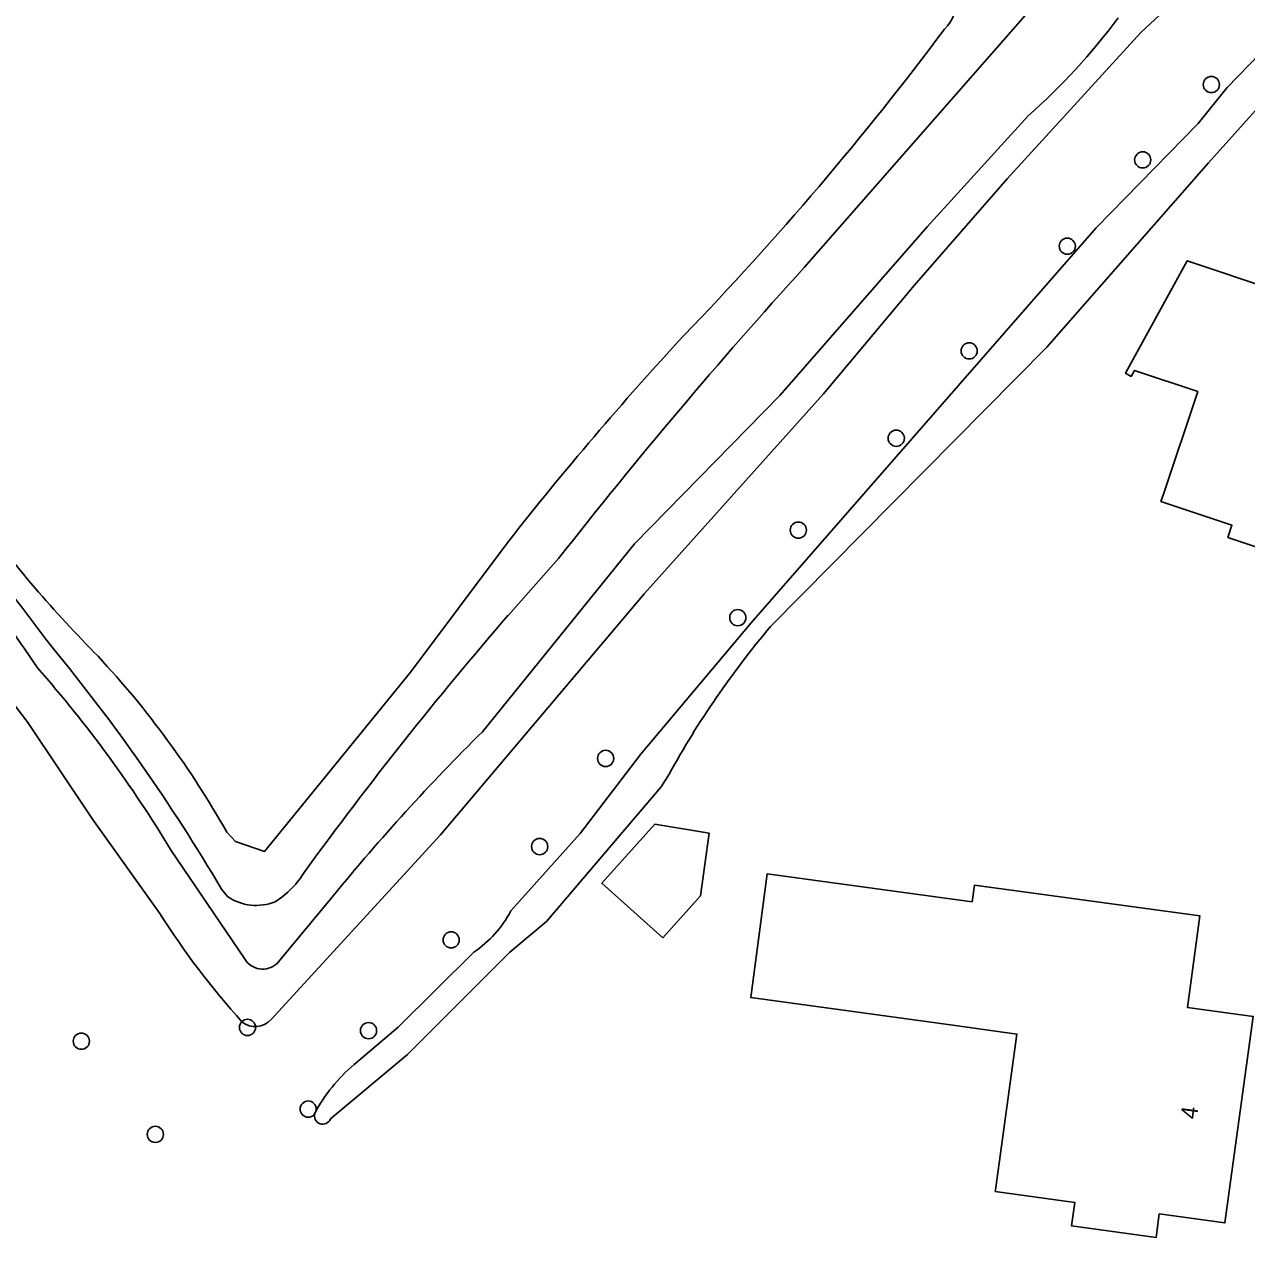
# Model space of a CAD drawing. Extents: x 161696 to 162377, y 380761 to 381673.
# Drawn here: x 161820.6 to 161894.4, y 380889 to 380962.2 of the extents above; entities that cross this region are included whole.
import ezdxf

# ---------------------------------------------------------------- set-up
doc = ezdxf.new("R2010")
doc.units = 0
for name, color, linetype in [('IMGEO_Boom', 7, 'Continuous'), ('IMGEO_Groenvoorziening', 7, 'Continuous'), ('IMGEO_Meer_plas_ven_vijver', 7, 'Continuous'), ('IMGEO_Pand', 7, 'Continuous'), ('IMGEO_Pand_nummerreeks', 7, 'Continuous')]:
    doc.layers.add(name, color=color, linetype=linetype)

msp = doc.modelspace()

# ---------------------------------------------------------------- linework, layer by layer
at = {"layer": 'IMGEO_Boom'}
for centre in [(161892.316, 380958.613), (161888.173, 380954.061), (161883.615, 380948.847), (161877.691, 380942.522), (161873.285, 380937.245), (161867.37, 380931.695), (161863.713, 380926.409), (161855.73, 380917.904), (161851.744, 380912.578), (161846.4, 380906.942), (161834.099, 380901.653), (161841.411, 380901.459), (161824.062, 380900.819), (161837.765, 380896.719), (161828.531, 380895.19)]:
    msp.add_circle(centre, 0.489, dxfattribs=at)
at = {"layer": 'IMGEO_Groenvoorziening'}
for points in [[(161890.992, 380963.938), (161889.178, 380962.795), (161888.049, 380961.767), (161879.992, 380952.907), (161874.365, 380946.481), (161868.891, 380939.924), (161858.069, 380927.868), (161845.75, 380913.287), (161835.524, 380902.132)], [(161828.8, 380908.528), (161824.729, 380914.242), (161820.832, 380920.076), (161816.792, 380925.368), (161812.56, 380930.508)], [(161832.847, 380913.452), (161833.367, 380912.893), (161835.131, 380912.284), (161843.974, 380923.135), (161849.842, 380930.991)]]:
    msp.add_lwpolyline(points, dxfattribs=at)
for centre, radius, start, end in [((161874.423, 380963.719), 2.502, 315.23013, 55.38582), ((161721.268, 381077.819), 193.462, 316.01453, 323.20983), ((162011.017, 380804.458), 204.91, 137.28297, 141.86566), ((161880.505, 380979.022), 78.053, 216.46984, 224.74709), ((161784.161, 380885.964), 55.91, 29.44897, 42.9712), ((161871.423, 380935.736), 50.566, 212.5521, 221.87896), ((161834.566, 380903.002), 1.294, 232.17583, 317.7467)]:
    msp.add_arc(centre, radius, start, end, dxfattribs=at)
at = {"layer": 'IMGEO_Meer_plas_ven_vijver'}
for points in [[(161881.363, 380963.1), (161867.724, 380947.551)], [(161898.49, 380960.955), (161892.147, 380953.884), (161882.378, 380942.741), (161865.694, 380925.863)], [(161891.512, 380956.258), (161893.282, 380958.444), (161895.242, 380960.46)], [(161848.287, 380919.518), (161857.473, 380930.863), (161866.252, 380939.835), (161875.146, 380950.013), (161881.261, 380956.728)], [(161849.996, 380908.69), (161854.199, 380913.376), (161857.841, 380918.147), (161864.514, 380926.091), (161885.359, 380949.949), (161891.512, 380956.258)], [(161852.893, 380929.987), (161849.854, 380926.552)], [(161859.566, 380916.954), (161859.086, 380916.182), (161852.157, 380908.058), (161849.953, 380906.192), (161843.758, 380900.025), (161839.114, 380896.129)], [(161829.498, 380912.335), (161833.913, 380905.812)], [(161832.887, 380909.553), (161832.531, 380910.004)], [(161835.867, 380905.495), (161839.292, 380909.632)], [(161840.535, 380899.404), (161843.2, 380901.675), (161847.767, 380906.206)]]:
    msp.add_lwpolyline(points, dxfattribs=at)
for centre, radius, start, end in [((161855.472, 380985.852), 38.901, 311.52417, 323.37165), ((162097.685, 380738.329), 310.895, 137.70358, 141.94108), ((161562.489, 380729.187), 325.109, 36.95355, 40.36514), ((161742.127, 380869.892), 95.642, 34.00137, 42.69487), ((162023.218, 380776.27), 229.434, 139.07933, 144.01499), ((161907.228, 380890.732), 54.4, 139.77431, 151.1819), ((161733.625, 380851.665), 114.83, 30.53384, 39.4523), ((161763.115, 380872.221), 77.561, 31.14362, 41.26455), ((161940.338, 380826.728), 130.703, 134.77098, 140.63262), ((161832.655, 380914.08), 5.756, 302.77592, 328.57957), ((161834.628, 380912.153), 3.129, 236.18645, 291.42543), ((161844.156, 380911.688), 6.565, 303.37135, 332.82266), ((161835.019, 380906.449), 1.276, 209.9344, 311.63583), ((161846.792, 380891.936), 9.743, 129.96068, 152.3411), ((161838.643, 380896.306), 0.503, 162.28511, 339.44102)]:
    msp.add_arc(centre, radius, start, end, dxfattribs=at)
at = {"layer": 'IMGEO_Pand'}
for points in [[(161904.606, 380949.376), (161901.633, 380940.472), (161900.683, 380940.788), (161900.051, 380938.888), (161905.097, 380937.205), (161902.371, 380929.046), (161898.075, 380930.482), (161897.828, 380929.743), (161893.314, 380931.252), (161893.562, 380931.992), (161889.275, 380933.425), (161889.424, 380933.871), (161891.494, 380940.065), (161887.672, 380941.343), (161887.466, 380940.984), (161887.136, 380941.173), (161890.851, 380947.961), (161896.162, 380946.187), (161897.967, 380951.593), (161904.606, 380949.376)], [(161861.989, 380913.379), (161861.455, 380909.606), (161859.179, 380907.066), (161855.499, 380910.364), (161858.694, 380913.929), (161861.989, 380913.379)], [(161877.874, 380909.249), (161878.009, 380910.24), (161891.624, 380908.386), (161890.871, 380902.862), (161894.845, 380902.314), (161893.139, 380889.842), (161889.176, 380890.385), (161888.981, 380888.958), (161883.879, 380889.657), (161884.074, 380891.083), (161879.269, 380891.741), (161879.303, 380891.989), (161880.571, 380901.253), (161876.707, 380901.782), (161864.501, 380903.453), (161865.489, 380910.935), (161877.874, 380909.249)]]:
    msp.add_lwpolyline(points, dxfattribs=at)

# ---------------------------------------------------------------- texts
at = {"layer": 'IMGEO_Pand_nummerreeks'}
msp.add_text('4', height=1, rotation=82.48472, dxfattribs=at).set_placement((161891.438, 380896.074))

doc.saveas('drawing.dxf')
